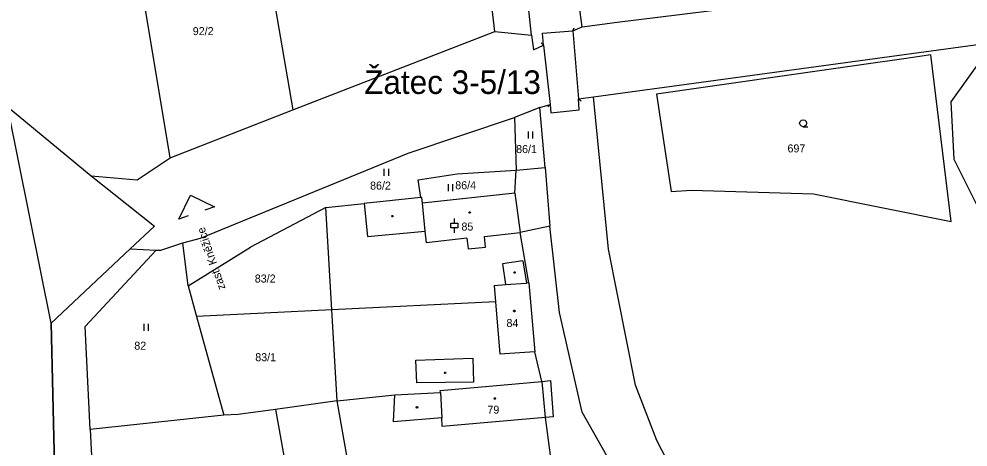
# Model space of a CAD drawing. Extents: x -812394 to -807601, y -1013097 to -1009266.
# Drawn here: x -809827.1 to -809625.5, y -1010903.7 to -1010812.8 of the extents above; entities that cross this region are included whole.
import ezdxf

# ---------------------------------------------------------------- set-up
doc = ezdxf.new("R2010")
doc.units = 0
for name, color, linetype in [('Default', 7, 'Continuous'), ('KLADY_ZMVM', 7, 'Continuous'), ('KN_HRANICE', 7, 'Continuous'), ('KN_KULTURY', 7, 'Continuous'), ('KN_PARCELY', 7, 'Continuous'), ('KN_SLUCKY', 7, 'Continuous'), ('obvod_stavby', 7, 'Continuous')]:
    doc.layers.add(name, color=color, linetype=linetype)

# ---------------------------------------------------------------- blocks, each defined once
blk = doc.blocks.new('4201')
at = {"layer": 'Default'}
blk.add_line((0, 0), (-0.5, -0.5), dxfattribs=at)
blk = doc.blocks.new('304')
at = {"layer": 'Default'}
blk.add_lwpolyline([(0, 0), (-0.38, 0.1), (-0.65, 0.37), (-0.75, 0.74), (-0.65, 1.11), (-0.38, 1.38), (-0.01, 1.48), (0.36, 1.38), (0.63, 1.11), (0.73, 0.73), (0.63, 0.35), (0.36, 0.08), (-0.02, -0.02), (0.98, -0.02)], dxfattribs=at)
blk = doc.blocks.new('306')
at = {"layer": 'Default'}
for p, q in [((-0.5, 1.5), (-0.5, 0)), ((0.5, 0), (0.5, 1.5))]:
    blk.add_line(p, q, dxfattribs=at)
blk = doc.blocks.new('318')
at = {"layer": 'Default'}
blk.add_line((0, 2), (0, 3), dxfattribs=at)
blk.add_lwpolyline([(0, 0), (0, 1), (-0.75, 1), (-0.75, 2), (0, 2), (0.75, 2), (0.75, 1), (0, 1)], dxfattribs=at)
blk = doc.blocks.new('402')
at = {"layer": 'Default'}
blk.add_lwpolyline([(0.09, 0.15), (0.18, 0), (0.09, -0.15), (-0.09, -0.15), (-0.18, 0), (-0.09, 0.15), (0.09, 0.15)], dxfattribs=at)

msp = doc.modelspace()

# ---------------------------------------------------------------- linework, layer by layer
at = {"layer": 'Default'}
msp.add_lwpolyline([(-809791.17, -1010854.59), (-809793.18, -1010855.28), (-809790.68, -1010850.2), (-809785.61, -1010852.7), (-809787.62, -1010853.38)], dxfattribs=at)
at = {"layer": 'KN_HRANICE'}
for p, q in [((-809776.12, -1010790.59), (-809768.91, -1010832.11)), ((-809718.25, -1010816.21), (-809720.85, -1010791.69)), ((-809707.49, -1010814.44), (-809710.32, -1010793.53)), ((-809795, -1010842.25), (-809802.82, -1010795.47)), ((-809726.02, -1010815.44), (-809727.35, -1010804.19)), ((-809700.6, -1010813.52), (-809643.49, -1010806.47)), ((-809709.48, -1010815.3), (-809707.49, -1010814.44)), ((-809707.49, -1010814.44), (-809701.59, -1010813.65)), ((-809701.59, -1010813.65), (-809700.6, -1010813.52)), ((-809768.91, -1010832.11), (-809726.02, -1010815.44)), ((-809726.02, -1010815.44), (-809718.25, -1010816.21)), ((-809718.25, -1010816.21), (-809717.84, -1010819.37)), ((-809715.88, -1010815.78), (-809709.48, -1010815.3)), ((-809715.65, -1010818.36), (-809715.88, -1010815.78)), ((-809705.08, -1010829.3), (-809609.07, -1010816.23)), ((-809717.84, -1010819.37), (-809715.65, -1010818.36)), ((-809622.36, -1010820.88), (-809629.15, -1010830.35)), ((-809716.45, -1010831.55), (-809714.29, -1010830.95)), ((-809714.29, -1010830.95), (-809714.1, -1010832.7)), ((-809708.23, -1010829.73), (-809705.08, -1010829.3)), ((-809708.1, -1010832.05), (-809708.23, -1010829.73)), ((-809701.84, -1010861.69), (-809705.08, -1010829.3)), ((-809629.15, -1010830.35), (-809628.52, -1010842.52)), ((-809828.94, -1010831.94), (-809811.76, -1010846.11)), ((-809795, -1010842.25), (-809768.91, -1010832.11)), ((-809716.45, -1010831.55), (-809721.87, -1010833.74)), ((-809715.34, -1010844.3), (-809716.45, -1010831.55)), ((-809714.1, -1010832.7), (-809708.1, -1010832.05)), ((-809744.44, -1010841.28), (-809721.87, -1010833.74)), ((-809721.87, -1010833.74), (-809721.48, -1010844.89)), ((-809802.04, -1010846.92), (-809795, -1010842.25)), ((-809788.59, -1010859.35), (-809744.44, -1010841.28)), ((-809628.52, -1010842.52), (-809623.05, -1010853.45)), ((-809734.04, -1010845.7), (-809721.48, -1010844.89)), ((-809721.76, -1010849.8), (-809721.48, -1010844.89)), ((-809721.48, -1010844.89), (-809715.34, -1010844.3)), ((-809715.34, -1010844.3), (-809714.35, -1010856.77)), ((-809811.76, -1010846.11), (-809802.04, -1010846.92)), ((-809811.76, -1010846.11), (-809806.99, -1010849.89)), ((-809742.28, -1010846.91), (-809734.04, -1010845.7)), ((-809741.74, -1010850.68), (-809742.28, -1010846.91)), ((-809806.99, -1010849.89), (-809798.33, -1010856.76)), ((-809741.74, -1010850.68), (-809753.76, -1010851.95)), ((-809741.55, -1010850.66), (-809741.74, -1010850.68)), ((-809741.42, -1010851.87), (-809741.55, -1010850.66)), ((-809721.76, -1010849.8), (-809741.42, -1010851.87)), ((-809761.95, -1010852.82), (-809777.96, -1010861.22)), ((-809761.95, -1010852.82), (-809753.76, -1010851.95)), ((-809760.65, -1010874.53), (-809761.95, -1010852.82)), ((-809803.49, -1010861.61), (-809798.33, -1010856.76)), ((-809714.35, -1010856.77), (-809720.67, -1010858.1)), ((-809712.26, -1010875.07), (-809714.35, -1010856.77)), ((-809718.78, -1010868.81), (-809720.67, -1010858.1)), ((-809796.98, -1010861.88), (-809792.34, -1010860.31)), ((-809792.34, -1010860.31), (-809788.59, -1010859.35)), ((-809791.19, -1010869.46), (-809792.34, -1010860.31)), ((-809791.19, -1010869.46), (-809777.96, -1010861.22)), ((-809820.27, -1010877.38), (-809803.49, -1010861.61)), ((-809813.07, -1010878.06), (-809797.95, -1010861.84)), ((-809803.49, -1010861.61), (-809797.95, -1010861.84)), ((-809797.95, -1010861.84), (-809796.98, -1010861.88)), ((-809696.17, -1010890.56), (-809701.84, -1010861.69)), ((-809726.19, -1010869.35), (-809723.78, -1010869.17)), ((-809723.78, -1010869.17), (-809719.27, -1010868.85)), ((-809718.78, -1010868.81), (-809719.27, -1010868.85)), ((-809718.78, -1010868.81), (-809717.54, -1010883.42)), ((-809791.19, -1010869.46), (-809789.4, -1010875.94)), ((-809726.19, -1010869.35), (-809725.89, -1010872.83)), ((-809725.89, -1010872.83), (-809760.65, -1010874.53)), ((-809760.65, -1010874.53), (-809789.4, -1010875.94)), ((-809759.51, -1010893.83), (-809760.65, -1010874.53)), ((-809707.45, -1010896.24), (-809712.26, -1010875.07)), ((-809820.27, -1010877.38), (-809819.54, -1010907.65)), ((-809789.4, -1010875.94), (-809783.61, -1010896.9)), ((-809811.97, -1010899.94), (-809813.07, -1010878.06)), ((-809716.06, -1010889.76), (-809717.54, -1010883.42)), ((-809716.06, -1010889.76), (-809714.21, -1010889.51)), ((-809714.21, -1010889.51), (-809713.65, -1010897.28)), ((-809737.62, -1010891.67), (-809716.06, -1010889.76)), ((-809691.58, -1010902.27), (-809696.17, -1010890.56)), ((-809759.51, -1010893.83), (-809747.26, -1010892.56)), ((-809747.26, -1010892.56), (-809737.6, -1010892.07)), ((-809737.6, -1010892.07), (-809737.62, -1010891.67)), ((-809759.51, -1010893.83), (-809772.62, -1010895.72)), ((-809754.39, -1010922.74), (-809759.51, -1010893.83)), ((-809783.61, -1010896.9), (-809811.97, -1010899.94)), ((-809780.58, -1010896.79), (-809783.61, -1010896.9)), ((-809772.62, -1010895.72), (-809780.58, -1010896.79)), ((-809772.62, -1010895.72), (-809767.28, -1010925.14)), ((-809713.65, -1010897.28), (-809715.33, -1010897.38)), ((-809715.33, -1010897.38), (-809714.24, -1010905.37)), ((-809688.11, -1010930.67), (-809707.45, -1010896.24)), ((-809811.97, -1010899.94), (-809810.23, -1010936.6)), ((-809685.82, -1010913.52), (-809691.58, -1010902.27))]:
    msp.add_line(p, q, dxfattribs=at)
msp.add_lwpolyline([(-809691.7, -1010828.74), (-809688.53, -1010849.4), (-809684.21, -1010849.11), (-809658.29, -1010849.93), (-809629.1, -1010855.77), (-809633.37, -1010820.41), (-809639.13, -1010821.28), (-809648.14, -1010822.51)], close=True, dxfattribs=at)
at = {"layer": 'KN_SLUCKY'}
for p, q in [((-809709.48, -1010815.3), (-809708.23, -1010829.73)), ((-809715.65, -1010818.36), (-809714.29, -1010830.95)), ((-809721.76, -1010849.8), (-809720.67, -1010858.1)), ((-809753.76, -1010851.95), (-809753.04, -1010859)), ((-809740.79, -1010857.85), (-809741.42, -1010851.87)), ((-809753.04, -1010859), (-809740.79, -1010857.85)), ((-809740.55, -1010860.29), (-809740.79, -1010857.85)), ((-809728.23, -1010858.97), (-809720.67, -1010858.1)), ((-809728.04, -1010861.21), (-809728.23, -1010858.97)), ((-809731.95, -1010859.34), (-809740.55, -1010860.29)), ((-809731.95, -1010859.34), (-809731.7, -1010861.58)), ((-809731.7, -1010861.58), (-809728.04, -1010861.21)), ((-809720.09, -1010864.16), (-809724.37, -1010864.8)), ((-809724.37, -1010864.8), (-809723.78, -1010869.17)), ((-809720.09, -1010864.16), (-809719.27, -1010868.85)), ((-809725.89, -1010872.83), (-809724.95, -1010883.96)), ((-809717.54, -1010883.42), (-809724.95, -1010883.96)), ((-809742.8, -1010885.24), (-809730.68, -1010884.82)), ((-809742.56, -1010890.05), (-809742.8, -1010885.24)), ((-809730.68, -1010884.82), (-809730.54, -1010889.91)), ((-809730.54, -1010889.91), (-809742.56, -1010890.05)), ((-809716.06, -1010889.76), (-809715.33, -1010897.38)), ((-809747.53, -1010898.29), (-809747.26, -1010892.56)), ((-809737.6, -1010892.07), (-809737.3, -1010897.44)), ((-809737.3, -1010897.44), (-809747.53, -1010898.29)), ((-809737.2, -1010899.28), (-809737.3, -1010897.44)), ((-809715.33, -1010897.38), (-809737.2, -1010899.28))]:
    msp.add_line(p, q, dxfattribs=at)
at = {"layer": 'obvod_stavby'}
msp.add_lwpolyline([(-809819.54, -1010907.68), (-809820.27, -1010877.38), (-809829.44, -1010832), (-809848.49, -1010834.46), (-809851.28, -1010798.84), (-809898.47, -1010814.6), (-809898.21, -1010828.41), (-809894.78, -1010861.65), (-809893.92, -1010865.41), (-809892.39, -1010868.68), (-809890.33, -1010872.36)], dxfattribs=at)

# ---------------------------------------------------------------- block references
at = {"layer": 'KN_KULTURY'}
for name, p in [('304', (-809660.52, -1010835.66)), ('306', (-809718.42, -1010838.2)), ('306', (-809749.07, -1010846.12)), ('306', (-809735.43, -1010849.36)), ('402', (-809747.77, -1010854.66)), ('318', (-809734.6, -1010858.16)), ('402', (-809731.38, -1010853.87)), ('402', (-809721.84, -1010866.6)), ('402', (-809721.89, -1010874.78)), ('306', (-809800.11, -1010879.02)), ('402', (-809736.58, -1010887.9)), ('402', (-809726.02, -1010893.37)), ('402', (-809742.55, -1010895.24))]:
    msp.add_blockref(name, p, dxfattribs=at)
at = {"layer": 'KN_SLUCKY'}
for p, rotation in [((-809709.48, -1010815.3), -162.55874399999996), ((-809715.65, -1010818.36), -88.016935), ((-809708.23, -1010829.73), 99.465473)]:
    msp.add_blockref('4201', p, dxfattribs=dict(at, rotation=rotation))
msp.add_blockref('4201', (-809714.29, -1010830.95), dxfattribs=at)

# ---------------------------------------------------------------- texts
at = {"layer": 'Default'}
msp.add_text('zast. Kněžice', height=1.75, rotation=108.9609, dxfattribs=at).set_placement((-809783.21, -1010869.98))
at = {"layer": 'KLADY_ZMVM'}
msp.add_text('Žatec 3-5/13', height=5, dxfattribs=at).set_placement((-809753.77, -1010828.71))
at = {"layer": 'KN_PARCELY'}
for s, p in [('92/2', (-809790.2, -1010816.22)), ('86/1', (-809721.5, -1010841.26)), ('697', (-809663.85, -1010841.12)), ('86/4', (-809734.43, -1010848.94)), ('86/2', (-809752.53, -1010849.01)), ('85', (-809733.12, -1010857.71)), ('83/2', (-809777.02, -1010868.74)), ('84', (-809723.55, -1010878.18)), ('82', (-809802.62, -1010883)), ('83/1', (-809776.92, -1010885.44)), ('79', (-809727.6, -1010896.58))]:
    msp.add_text(s, height=1.7, dxfattribs=at).set_placement(p)

doc.saveas('drawing.dxf')
